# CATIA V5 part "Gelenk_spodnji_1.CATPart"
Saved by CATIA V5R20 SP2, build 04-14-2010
Part number: Gelenk_spodnji_1
Bounding box of the stored display mesh (mm): x -4.776 to 4.799, y 0 to 25, z -29.799 to 29.799
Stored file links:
  C:\Documents and Settings\Administrator\My Documents\Hobi_dokumenti\CAD_CNC\Clap_CATIA\Gelenk_spodnji_1.CATPart
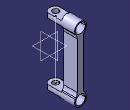
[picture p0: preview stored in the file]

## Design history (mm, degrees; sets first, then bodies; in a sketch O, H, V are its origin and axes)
Set1
  Point1: type Center, Curve edge [face of Pocket1 from Sketch2.L5 | face of Pocket2 from Sketch3.A1]
  Point2: type Center, Curve edge [face of Mirror1 | face of Mirror1]
  Line1: type PtPt, FirstPoint Point2, SecondPoint Point1
Body1 (main body)
  Sketch1 on xy-plane, origin (0, 0, 0), H (1, 0, 0), V (0, 1, 0)
    line L1 (0, 0) -> (-4.8, 0)
    line L2 (-4.8, 0) -> (-4.8, 25)
    line L3 (-4.8, 25) -> (0, 25)
    line L4 (0, 25) -> (0, 0)
    point P1 (-4.8, 0)
    point P3 (0, 25)
    distance O P1 = 4.8
    distance P3 O = 25
    horizontal: L1 H, L3 H
    vertical: L2 V, L4 V
    perpendicularity: L1 L2
  Shaft1: profile Sketch1, axis Sketch1.L4, angle 360
  Translate1: Direction xy-plane, Length 25, ToTransfor Shaft1
  Sketch2 on yz-plane, origin (0, 0, 0), H (0, 1, 0), V (0, 0, 1)
    line L1 (-3.9957, 30.9) -> (14, 30.9)
    line L2 (14, 30.9) -> (14, 26.9)
    line L3 (14, 26.9) -> (-3.9957, 26.9)
    line L4 (-3.9957, 26.9) -> (-3.9957, 30.9)
    point P5 (-3.9957, 23.1)
    line L5 (-3.9957, 23.1) -> (14, 23.1)
    line L6 (14, 23.1) -> (14, 19.1)
    line L7 (14, 19.1) -> (-3.9957, 19.1)
    line L8 (-3.9957, 19.1) -> (-3.9957, 23.1)
    point P7 (14, 19.1)
    reference projected line E1 through (0, 25) direction (1, 0) from axis of face of Shaft1 from Sketch1.L2
    reference projected line E2 through (0, 25) direction (1, 0) from axis of face of Shaft1 from Sketch1.L2
    reference projected line E3 (0, 29.8) -> (0, 20.2) from edge [face of Shaft1 from Sketch1.L1 | face of Shaft1 from Sketch1.L2]
    distance E1 L5 = 1.9
    distance E2 L3 = 1.9
    distance E3 L2 = 14
    length L8 = 4
    length L4 = 4
    horizontal: L1 H, L3 H, L5 H, L7 H
    vertical: L2 V, L4 V, L6 V, L8 V
    coincidence: P5 L4, P7 L2
  Pocket1: profile Sketch2, direction (1, 0, 0), length 20, mirrored extent
  Sketch3 on xy-plane, origin (0, 0, 0), H (1, 0, 0), V (0, 1, 0)
    circle A1 centre (0, 4.9462) radius 2.5
    point P1 (0, 4.9462)
    arc A2 centre (0, 4.9462) radius 5 from (-5, 4.9462) to (5, 4.9462) ccw
    line L1 (8.2326, 4.9462) -> (5, 4.9462)
    line L2 (-8.288, 4.9462) -> (-8.288, -1.7558)
    line L3 (-8.288, -1.7558) -> (8.2326, -1.7558)
    line L4 (8.2326, -1.7558) -> (8.2326, 4.9462)
    point P6 (-5, 4.9462)
    line L5 (-5, 4.9462) -> (-8.288, 4.9462)
    radius A1 = 2.5
    radius A2 = 5
    coincidence: P1 V, L1 P6
    horizontal: L1 H, L3 H, L5 H
    vertical: L2 V, L4 V
  Pocket2: profile Sketch3, direction (0, 0, 1), through (limit type 6)
  Mirror1: of the body so far, about xy-plane
  Sketch4 on face of Shaft1 from Sketch1.L3, origin (0, 25, 0), H (-1, 0, 0), V (0, 0, 1)
    line L1 (-2.5, 25) -> (2.5, 25)
    line L2 (2.5, 25) -> (2.5, -25)
    line L3 (2.5, -25) -> (-2.5, -25)
    line L4 (-2.5, -25) -> (-2.5, 25)
    distance V L2 = 2.5
    length L4 = 50
    distance H L3 = 25
    distance V L4 = 2.5
    horizontal: L1 H, L3 H
    vertical: L2 V, L4 V
  Pad1: profile Sketch4, direction (0, -1, 0), up to face of Pocket1 from Sketch2.L6
  Fillet1: radius 5, on edge [face of Shaft1 from Sketch1.L2 | face of Pad1 from Sketch4.L4]; edge [face of Pad1 from Sketch4.L2 | face of Shaft1 from Sketch1.L2]; edge [face of Pad1 from Sketch4.L4 | face of Mirror1]; edge [face of Mirror1 | face of Pad1 from Sketch4.L2]
  Sketch5 on face of Mirror1, origin (0, 25, 0), H (-1, 0, 0), V (0, 0, 1)
    circle A1 centre (0, 25) radius 4
    point P1 (0, 25)
    circle A2 centre (0, -25) radius 4
    point P2 (0, -25)
    reference intersected line E1 through (0, 0) direction (-1, 0) from xy-plane
    reference intersected line E2 through (0, 0) direction (0, -1) from yz-plane
    radius A1 = 4
    radius A2 = 4
    distance P2 H = 25
    distance P1 H = 25
    coincidence: P1 V, P2 V, E2 P1
    vertical: E2 V
    horizontal: E1 H
  Pocket3: profile Sketch5, direction (0, -1, 0), length 10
